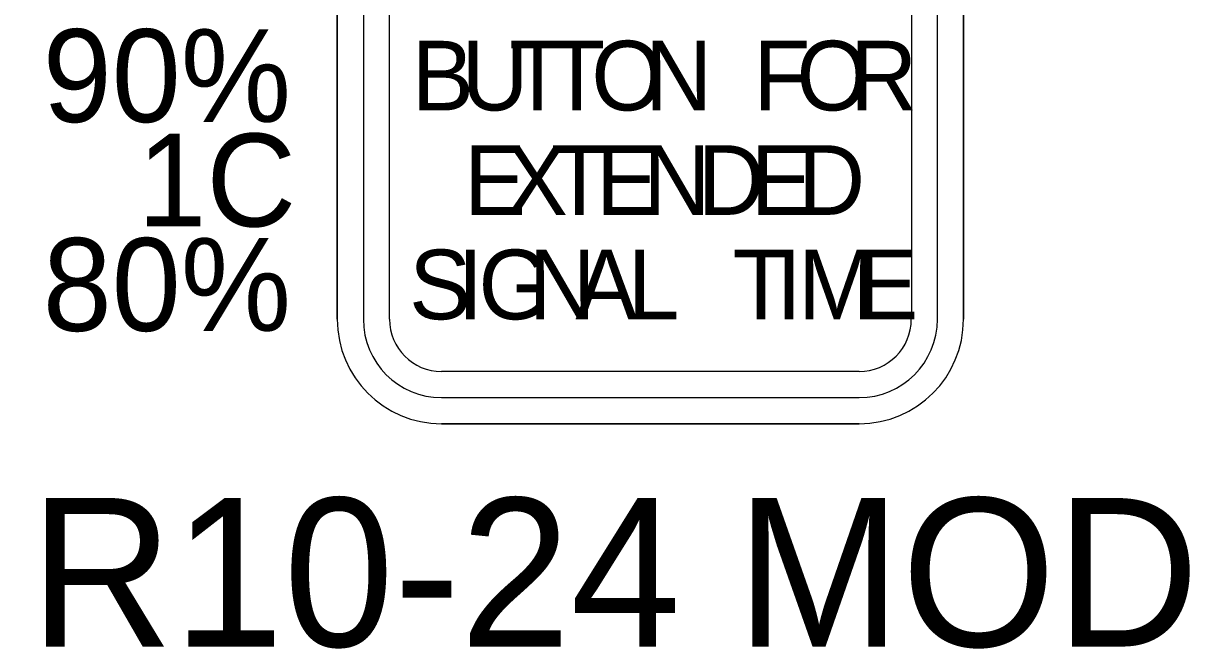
# Model space of a CAD drawing. Extents: x 99982 to 100176, y 99905 to 100011.
# Drawn here: x 100009.271 to 100009.837, y 99915.077 to 99915.38 of the extents above; entities that cross this region are included whole.
import ezdxf

# ---------------------------------------------------------------- set-up
doc = ezdxf.new("R2010")
doc.units = 0
doc.layers.add('TR_SN_ConstructionSigns', color=7, linetype='Continuous')

msp = doc.modelspace()

# ---------------------------------------------------------------- linework, layer by layer
at = {"layer": 'TR_SN_ConstructionSigns'}
for p, q in [((100009.42363, 99915.23704), (100009.42363, 99915.64204)), ((100009.42363, 99915.64204), (100009.42363, 99915.23704)), ((100009.42363, 99915.64204), (100009.42363, 99915.23704)), ((100009.43628, 99915.64204), (100009.43628, 99915.23704)), ((100009.44894, 99915.23704), (100009.44894, 99915.64204)), ((100009.70207, 99915.64204), (100009.70207, 99915.23704)), ((100009.71472, 99915.23704), (100009.71472, 99915.64204)), ((100009.72738, 99915.64204), (100009.72738, 99915.23704)), ((100009.72738, 99915.23704), (100009.72738, 99915.64204)), ((100009.72738, 99915.23704), (100009.72738, 99915.64204)), ((100009.67675, 99915.21173), (100009.47425, 99915.21173)), ((100009.47425, 99915.19907), (100009.67675, 99915.19907)), ((100009.67675, 99915.18641), (100009.47425, 99915.18641)), ((100009.47425, 99915.18641), (100009.67675, 99915.18641)), ((100009.47425, 99915.18641), (100009.67675, 99915.18641))]:
    msp.add_line(p, q, dxfattribs=at)
for centre, radius, start, end in [((100009.47425, 99915.23704), 0.05063, 180, 270), ((100009.47425, 99915.23704), 0.05063, 180, 270), ((100009.47425, 99915.23704), 0.05063, 180, 270), ((100009.47425, 99915.23704), 0.03797, 180, 270), ((100009.47425, 99915.23704), 0.02531, 180, 270), ((100009.67675, 99915.23704), 0.05063, 270, 0), ((100009.67675, 99915.23704), 0.05063, 270, 0), ((100009.67675, 99915.23704), 0.03797, 270, 0), ((100009.67675, 99915.23704), 0.02531, 270, 0), ((100009.67675, 99915.23704), 0.05063, 270, 0)]:
    msp.add_arc(centre, radius, start, end, dxfattribs=at)

# ---------------------------------------------------------------- texts
for s, height, p in [('1C, 90%', 0.045, (100009.17043, 99915.33266)), ('B', 0.03375, (100009.45976, 99915.33829)), ('U', 0.03375, (100009.48382, 99915.33829)), ('T', 0.03375, (100009.50697, 99915.33829)), ('T', 0.03375, (100009.52601, 99915.33829)), ('O', 0.03375, (100009.54687, 99915.33829)), ('N', 0.03375, (100009.57285, 99915.33829)), ('F', 0.03375, (100009.6255, 99915.33829)), ('O', 0.03375, (100009.64636, 99915.33829)), ('R', 0.03375, (100009.67235, 99915.33829)), ('1C', 0.045, (100009.32672, 99915.28204)), ('E', 0.03375, (100009.48505, 99915.28766)), ('X', 0.03375, (100009.5053, 99915.28766)), ('T', 0.03375, (100009.52724, 99915.28766)), ('E', 0.03375, (100009.54918, 99915.28766)), ('N', 0.03375, (100009.57213, 99915.28766)), ('D', 0.03375, (100009.59845, 99915.28766)), ('E', 0.03375, (100009.6241, 99915.28766)), ('D', 0.03375, (100009.64705, 99915.28766)), ('1C, 80%', 0.045, (100009.17043, 99915.23141)), ('S', 0.03375, (100009.45849, 99915.23704)), ('I', 0.03375, (100009.48198, 99915.23704)), ('G', 0.03375, (100009.49211, 99915.23704)), ('N', 0.03375, (100009.51641, 99915.23704)), ('A', 0.03375, (100009.53909, 99915.23704)), ('L', 0.03375, (100009.56447, 99915.23704)), ('T', 0.03375, (100009.61543, 99915.23704)), ('I', 0.03375, (100009.63642, 99915.23704)), ('M', 0.03375, (100009.64709, 99915.23704)), ('E', 0.03375, (100009.6753, 99915.23704))]:
    msp.add_text(s, height=height, dxfattribs=at).set_placement(p)
msp.add_text('R10-24 MOD', height=0.072, rotation=360, dxfattribs=at).set_placement((100009.27452, 99915.07841))

doc.saveas('drawing.dxf')
